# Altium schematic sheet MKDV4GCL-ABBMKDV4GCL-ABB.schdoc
size 127 x 101 mm
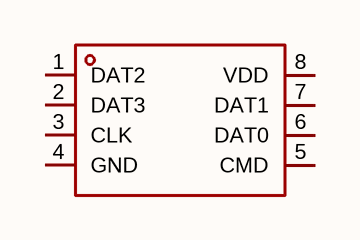
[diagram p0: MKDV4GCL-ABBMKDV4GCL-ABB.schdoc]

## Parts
U?  mkdv4gcl-abb  [LGA-8_L6.0-W8.0-P1.27-TL]  (value not drawn)

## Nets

Not connected (* = marked no-connect by the designer): U? 1(DAT2) 2(DAT3) 3(CLK) 4(GND) 5(CMD) 6(DAT0) 7(DAT1) 8(VDD)

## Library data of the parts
U? = mkdv4gcl-abb: 存储容量:4Gbit;时钟频率(fc):50MHz;工作电压:2.7V~3.6V;; Manufacturer: MK(米客方德); AddInBom: yes; ModelId: 1f88d973af574684b0007f41a35ee8d9; ModelName: LGA-8_L6.0-W8.0-H0.8-P1.27; ModelTransform: 314.96,236.22,0,0,0,0,0,0.005,0; Memory Size: 4Gbit; Interface: SD接口；SPI; Clock Frequency: 50MHz; Standby Supply Current: 170uA; Program / Erase Cycles: 6万次; ECC: 有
